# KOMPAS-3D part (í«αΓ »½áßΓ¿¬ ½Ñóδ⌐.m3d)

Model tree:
1. Эскиз:1
2. Операция выдавливания:1
     Расстояние 1 = 2
3. Эскиз:2
4. Операция выдавливания:3
     Расстояние 1 = 2
5. Эскиз:4
6. Вырезать элемент выдавливания:2
     Расстояние 1 = 4

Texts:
  борт пластик левый
  stalker61
  Полипропилен  ГОСТ 26996-86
